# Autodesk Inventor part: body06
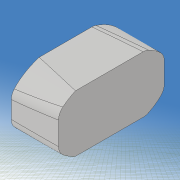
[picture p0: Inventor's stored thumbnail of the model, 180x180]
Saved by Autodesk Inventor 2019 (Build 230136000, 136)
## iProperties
Created: 2020-12
Part Number: body06
Material: 一般
Document SubType Name: Modeling
Designer: kikut
Density: 1 g/cm^3
Appearance: 既定
Mass: 87.6477 g
Surface Area: 156.124 cm^2
Volume: 87.6477 cm^3
Author: kikut
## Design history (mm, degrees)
sketch "スケッチ1"
  geometry: L1 (-100, -20)-(100, -20); L2 (100, -20)-(100, 20); L3 (100, 20)-(-100, 20); L4 (-100, 20)-(-100, -20); L5 (-100, -20)-(100, 20); L6 (100, -20)-(-100, 20); 1 further point
  constraints: 12 end point, 2 midpoint, 2 parallel, 1 horizontal, 1 perpendicular
  dimensions: "d0" = 40 distance of L3.end L1.start; "d1" = 200 distance of L2.end L3.end
extrude "押し出し1" new body sketch "スケッチ1" stored distance "d2" = 60; taper "d3" = 0 deg
sketch "スケッチ2"
  geometry: L1 (0, -60)-(0, 0) reference; L2 (200, -60)-(200, 0) reference; L3 (0, 0)-(200, 0) reference; L4 (200, -60)-(0, -60) reference; L5 (0, -26)-(0, -32); L6 (194, -10)-(194, -13); L7 (194, -13)-(174, -33); L8 (174, -33)-(200, -58); L9 (-20, 20)-(220, 20); L10 (220, 20)-(220, -100); L11 (220, -100)-(-20, -100); L12 (-20, -100)-(-20, 20); 12 further points
  constraints: 16 end point, 4 point on line, 2 parallel, 2 vertical, 1 horizontal, 1 perpendicular, 14 other
  dimensions: "d4" = 32 distance from line of point (32, -12) L1; "d5" = 50 horizontal distance of point (32, -12) point (82, -11); "d6" = 50 horizontal distance of point (132, -17) point (82, -11); "d7" = 12 distance from line of point (32, -12) L3; "d8" = 11 distance from line of point (82, -11) L3; "d10" = 17 distance from line of point (132, -17) L3; "d11" = 26 distance from line of L5.start L3; "d12" = 0 distance from line of point (200, -60) L4; "d13" = 28 distance from line of L5.end L4; "d14" = 12 distance from line of point (28, -48) L4; "d15" = 10 distance from line of point (80, -50) L4; "d16" = 16 distance from line of point (130, -44) L4; "d17" = 28 distance from line of point (28, -48) L1; "d19" = 50 horizontal distance of point (130, -44) point (80, -50); "d20" = 80 distance from line of point (80, -50) L1; "d21" = 6 distance from line of L6.start L2; "d22" = 36 distance from line of point (164, -24) L2; "d23" = 24 distance from line of point (176, -20) L2; "d24" = 10 distance from line of L6.start L3; "d25" = 20 distance from line of point (176, -20) L3; "d26" = 24 distance from line of point (164, -24) L3; "d27" = 40 distance from line of point (160, -40) L2; "d28" = 25 distance from line of point (175, -47.5) L2; "d29" = 12.5 distance from line of point (175, -47.5) L4; "d30" = 20 distance from line of L4 point (160, -40); "d31" = 3 distance of L6.start L6.end; "d32" = 33 distance from line of L7.end L3; "d33" = 26 distance from line of L7.end L2; "d34" = 2 distance of L8.end L2.start; "d35" = 120 distance of L11.end L9.start; "d36" = 240 distance of L10.end L11.end; "d37" = 20 distance between parallel lines of L1 L12; "d38" = 20 distance between parallel lines of L3 L9
extrude "押し出し2" cut sketch "スケッチ2" extent not by distance; stored distance "d39" = 0.02; taper "d40" = 0 deg
sketch "スケッチ8"
  geometry: L1 (-100, -20)-(-100, 20) reference; L2 (100, 20)-(100, -20) reference; L3 (-142.805, 0)-(142.831, 0) reference; L4 (110, 30)-(-110, 30); L5 (-110, 30)-(-110, -30); L6 (-110, -30)-(110, -30); L7 (110, -30)-(110, 30); L8 (110, 30)-(-110, -30); L9 (-110, 30)-(110, -30); L10 (-100, -2)-(-100, 2); L11 (100, -3)-(100, 3); 7 further points
  constraints: 16 end point, 4 point on line, 2 midpoint, 2 parallel, 2 perpendicular, 1 collinear, 1 horizontal, 10 other
  dimensions: "d93" = 2 vertical distance of point (0, 0) L10.end; "d94" = 2 vertical distance of L10.start point (0, 0); "d95" = 35 distance from line of point (-65, -10) L1; "d96" = 0 horizontal distance of point (-65, 10) point (-65, -10); "d97" = 10 vertical distance of point (0, 0) point (-65, -10); "d98" = 10 vertical distance of point (-65, 10) point (0, 0); "d99" = 100 distance from line of point (0, -10) L1; "d100" = 0 horizontal distance of point (0, 10) point (0, -10); "d101" = 10 distance of point (0, -10) point (0, 0); "d102" = 10 distance of point (0, 0) point (0, 10); "d103" = 160 distance from line of point (60, -4) L1; "d104" = 0 horizontal distance of point (60, 4) point (60, -4); "d105" = 4 distance from line of L3 point (60, -4); "d106" = 4 distance from line of L3 point (60, 4); "d107" = 3 distance from line of L11.start L3; "d108" = 3 distance from line of L11.end L3; "d109" = 220 distance of L5.end L6.end; "d110" = 60 distance of L4.end L5.end
extrude "押し出し6" cut sketch "スケッチ8" extent not by distance; stored distance "d111" = 10; taper "d112" = 0 deg
sketch "スケッチ9" dims "d113" = 20, "d114" = 12
  geometry: L1 (-29, -18)-(21, -18); L2 (21, -18)-(21, 22); L3 (21, 22)-(-29, 22); L4 (-29, 22)-(-29, -18); L5 (-29, -18)-(21, 22); L6 (21, -18)-(-29, 22); 2 further points; 1 other entity
  constraints: 12 end point, 2 midpoint, 2 parallel, 1 coincident, 1 horizontal, 1 perpendicular, 2 other
  dimensions: "d115" = 50 distance of L2.end L3.end; "d116" = 40 distance of L1.end L2.end
extrude "押し出し7" cut sketch "スケッチ9" distance "d117" = 150; taper "d118" = 0 deg
fillet "フィレット4" dims "d119" = 4
fillet "フィレット5" dims "d120" = 4
fillet "フィレット6" dims "d121" = 2
node "作業平面2"
sketch "スケッチ10"
  geometry: L1 (0, -41.439)-(0, 38.458) reference; L2 (141.833, 0)-(-140.631, 0) reference; L3 (82.55, 12.983)-(81.45, -4.983); A1 r 9 centre (82, 4) between (82.55, 12.983) and (81.45, -4.983); 1 further point
  constraints: 2 end point, 2 point on circle, 1 centre point
  dimensions: "d123" = 82 distance from line of L1 A1.centre; "d124" = 4 distance from line of L2 A1.centre; "d125" = 9 radius of A1; "d126" = 180 deg dimension on A1.centre L3.end L3.start; "d127" = 90 deg dimension on L3.end point (0, 0) A1.centre
revolve "回転1" sketch "スケッチ10" stored, may be unused: angle "d128" = 90 deg
mirror "ミラー1"
sketch "スケッチ11"
  geometry: L1 (10, 30)-(-5, 30); L2 (-5, 30)-(-5, -30); L3 (-5, -30)-(10, -30); L4 (10, -30)-(10, 30); L5 (0, -40.648)-(0, 34.486) reference; L6 (140.69, 0)-(-139.196, 0) reference; L7 (120, 53.792)-(-120, 53.792); L8 (-120, 53.792)-(-120, -46.208); L9 (-120, -46.208)-(120, -46.208); L10 (120, -46.208)-(120, 53.792); 1 further point
  constraints: 16 end point, 4 parallel, 2 horizontal, 2 perpendicular, 2 other
  dimensions: "d130" = 15 distance of L1.start L1.end; "d131" = 60 distance of L3.end L1.start; "d132" = 100 distance of L9.end L7.start; "d133" = 240 distance of L7.start L7.end; "d136" = 10 distance between parallel lines of L4 L5
extrude "押し出し8" cut sketch "スケッチ11" stored distance "d134" = 40; taper "d135" = 0 deg
node "ソリッド1"
other parameters: "d122" = -1
